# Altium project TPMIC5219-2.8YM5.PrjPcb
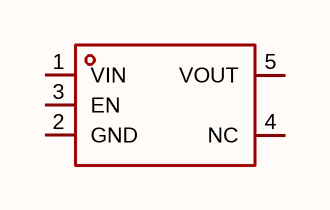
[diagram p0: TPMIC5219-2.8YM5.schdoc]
1 sheet, 1 parts. Net scope: global (net labels, ports and power ports of the same name join across sheets).

## Sheet TPMIC5219-2.8YM5.schdoc
size 127 x 101 mm

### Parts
U?  tpmic5219-2.8ym5  [SOT-23-5_L2.9-W1.6-P0.95-LS2.8-BR]  (value not drawn)

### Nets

Not connected (* = marked no-connect by the designer): U? 1(VIN) 2(GND) 3(EN) 4(NC) 5(VOUT)

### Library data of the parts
U? = tpmic5219-2.8ym5: 输出类型:固定;工作电压:20V;输出电压:2.8V;输出电流:500mA;电源纹波抑制比(PSRR):70dB@(1kHz);输出极性:正极;; Manufacturer: TECH PUBLIC(台舟); AddInBom: yes; ModelId: 7ba65df16e7b4570af156e925f9c37fe; ModelTransform: 114.173,114.173,0,90,0,0,0,0,0; Output Type: 固定; Voltage - Supply: 20V; Output Voltage: 2.8V; Output Current: 500mA; standby current: 1.5uA; Output Configuration: 正极; Number of Outputs: 1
